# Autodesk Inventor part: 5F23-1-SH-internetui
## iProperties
Created: 2010-01
Part Number: 5F23-1-SH-internetui
Document SubType Name: Modeling
Designer: Darius
Author: Darius
Translation Standard: STEP AP203
File Name: 5F23-1-SH.STEP
Preprocessor: SolidWorks 2003240
Postprocessor: Build: 272, Release: 10 SP3a - Date: Thu 12/15/2005
Sent Units: MILLIMETERS
Uncertainty: 1e-05
